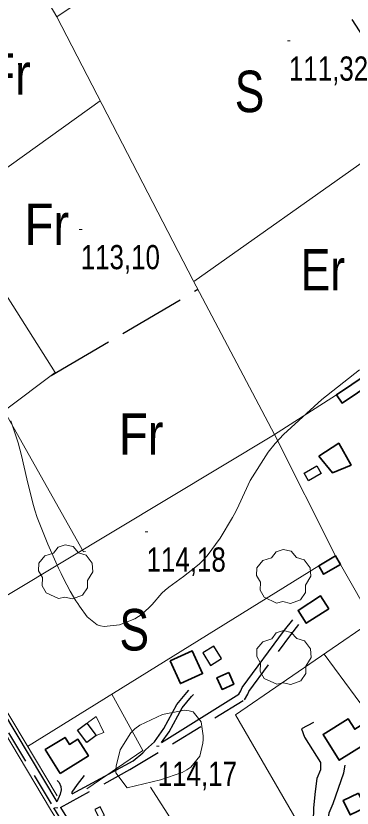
# Model space of a CAD drawing. Extents: x 487425 to 492029, y 4383576 to 4386788.
# Drawn here: x 490540.5 to 490662, y 4386018.5 to 4386304.9 of the extents above; entities that cross this region are included whole.
import ezdxf
from ezdxf.enums import TextEntityAlignment as Align

# ---------------------------------------------------------------- set-up
doc = ezdxf.new("R2010")
doc.units = 0
doc.header["$LTSCALE"] = 4
doc.linetypes.add('LONG_DASHED', pattern=[7.5, 6, -1.5])
doc.linetypes.add('MEDIUM_DASHED', pattern=[4.5, 3, -1.5])
for name, color, linetype, lineweight in [('21', 7, 'Continuous', 25), ('25', 7, 'LONG_DASHED', 25), ('29', 7, 'Continuous', 13), ('38', 7, 'Continuous', 25), ('47', 7, 'Continuous', 35), ('51', 7, 'Continuous', 13), ('7', 7, 'Continuous', 13), ('9', 7, 'Continuous', 13)]:
    doc.layers.add(name, color=color, linetype=linetype, lineweight=lineweight)
doc.layers.add('31', color=7, linetype='Continuous')

msp = doc.modelspace()

# ---------------------------------------------------------------- linework, layer by layer
at = {"layer": '21'}
for points in [[(490650.89, 4386139.47), (490646.27, 4386136.8), (490644.67, 4386139.56), (490649.29, 4386142.23)], [(490608.04, 4386074.58), (490610.86, 4386070.09), (490614.86, 4386072.61), (490612.04, 4386077.1)], [(490566.16, 4386049.22), (490569.52, 4386044.78), (490566.16, 4386042.23), (490562.79, 4386046.66)], [(490569.04, 4386018.01), (490570.63, 4386014.86), (490572.55, 4386015.83), (490570.96, 4386018.98)]]:
    msp.add_lwpolyline(points, close=True, dxfattribs=at)
at = {"layer": '25'}
for p, q in [((490629.52, 4386354.13), (490676.75, 4386280.46)), ((490553.28, 4386174.9), (490606.28, 4386206.06))]:
    msp.add_line(p, q, dxfattribs=at)
at = {"layer": '29'}
for points in [[(490555.93, 4386094.25), (490551.39, 4386096.37), (490549.98, 4386098.91), (490550.08, 4386101.89), (490548.71, 4386104.3), (490548.75, 4386107.05), (490550.91, 4386109.65), (490554.1, 4386110.65), (490555.75, 4386112.84), (490558.32, 4386113.67), (490561.18, 4386113.02), (490563.13, 4386110.75), (490565.94, 4386109.93), (490568.07, 4386107.08), (490568.31, 4386103.95), (490566.43, 4386100.8), (490566.43, 4386098.12), (490564.61, 4386095.51), (490560.99, 4386094.17), (490558.22, 4386094.8)], [(490634.73, 4386092.59), (490630.19, 4386094.71), (490628.78, 4386097.25), (490628.88, 4386100.23), (490627.51, 4386102.64), (490627.55, 4386105.39), (490629.71, 4386107.99), (490632.9, 4386108.99), (490634.55, 4386111.18), (490637.12, 4386112.01), (490639.98, 4386111.36), (490641.93, 4386109.09), (490644.74, 4386108.27), (490646.87, 4386105.42), (490647.11, 4386102.29), (490645.23, 4386099.14), (490645.23, 4386096.46), (490643.41, 4386093.85), (490639.79, 4386092.51), (490637.02, 4386093.14)], [(490634.79, 4386063.27), (490630.25, 4386065.39), (490628.84, 4386067.93), (490628.94, 4386070.91), (490627.57, 4386073.32), (490627.61, 4386076.07), (490629.77, 4386078.67), (490632.96, 4386079.67), (490634.61, 4386081.86), (490637.18, 4386082.69), (490640.04, 4386082.04), (490641.99, 4386079.77), (490644.8, 4386078.95), (490646.93, 4386076.1), (490647.17, 4386072.97), (490645.29, 4386069.82), (490645.29, 4386067.14), (490643.47, 4386064.53), (490639.85, 4386063.19), (490637.08, 4386063.82)]]:
    msp.add_lwpolyline(points, close=True, dxfattribs=at)
at = {"layer": '38', "linetype": 'MEDIUM_DASHED'}
msp.add_line((490556.58, 4386018.73), (490581.74, 4386032.41), dxfattribs=at)
at = {"layer": '38'}
for points in [[(490458.1, 4386192.65), (490473.89, 4386164.44), (490477.06, 4386159.29), (490478.72, 4386157.31), (490478.82, 4386156.45), (490478.96, 4386154.34), (490479.1, 4386151.81), (490479.32, 4386150.49), (490479.53, 4386149.03), (490479.9, 4386147.85), (490480.34, 4386145.7), (490481.44, 4386143.24), (490481.88, 4386141.61), (490483.93, 4386138.01), (490497.43, 4386116.24), (490530.41, 4386062.29), (490555.36, 4386020.73)], [(490593.1, 4386042.18), (490621.05, 4386059.68), (490621.76, 4386060.91), (490622.24, 4386062.11), (490637.63, 4386082.82), (490640.57, 4386086.57)], [(490560.87, 4386023.62), (490582.89, 4386035.6), (490586.38, 4386038.49), (490587.4, 4386039.58), (490590.55, 4386042.5), (490594.02, 4386047.29), (490598.71, 4386056.02), (490602.23, 4386060.29), (490603.01, 4386061.14)], [(490648.12, 4386049.49), (490643.76, 4386047.18), (490644.8, 4386044.18), (490650.62, 4386035.01), (490650.54, 4386032.31), (490649.33, 4386029.24), (490648.72, 4386024.52), (490648.1, 4386018.6), (490647.93, 4386013.65), (490647.3, 4386009.54)], [(490652.95, 4386010.31), (490653.79, 4386016.78), (490655.15, 4386020.23), (490659.08, 4386031.31), (490659.54, 4386034.08)], [(490560.87, 4386023.62), (490560.84, 4386024.33), (490562.72, 4386027.1), (490565.36, 4386030.24)], [(490555.45, 4386028.55), (490556.13, 4386027.8), (490556.72, 4386026.3), (490556.87, 4386025.1), (490556.49, 4386023.6), (490555.36, 4386020.73)], [(490556.58, 4386018.73), (490583.48, 4385975.5), (490583.94, 4385974.43), (490584.01, 4385974.39), (490585.05, 4385974.45), (490585.95, 4385974.66), (490586.6, 4385974.87), (490587.45, 4385975.16), (490590.25, 4385976.62)]]:
    msp.add_lwpolyline(points, dxfattribs=at)
at = {"layer": '38', "linetype": 'MEDIUM_DASHED'}
for points in [[(490505.07, 4386099.62), (490528.57, 4386061.18), (490554.09, 4386018.66), (490581.57, 4385974.5), (490582.24, 4385972.95), (490583.46, 4385972.21), (490583.77, 4385972.22)], [(490581.74, 4386032.41), (490623.13, 4386057.68), (490624.28, 4386059.68), (490624.7, 4386060.72), (490639.85, 4386081.12), (490642.77, 4386084.84)], [(490593.1, 4386042.18), (490595.93, 4386046.09), (490600.59, 4386054.76), (490603.93, 4386058.81), (490604.67, 4386059.62)]]:
    msp.add_lwpolyline(points, dxfattribs=at)
at = {"layer": '47'}
for points in [[(490656.35, 4386167.93), (490667.52, 4386175.42), (490669.56, 4386172.39), (490658.39, 4386164.9)], [(490649.98, 4386145.76), (490654.99, 4386139.67), (490661.67, 4386142.5), (490657.19, 4386150.38)], [(490649.94, 4386106.09), (490656.04, 4386109.64), (490657.81, 4386106.59), (490651.71, 4386103.04)], [(490653.56, 4386090.56), (490645.43, 4386085.36), (490642.47, 4386089.99), (490650.6, 4386095.19)], [(490596.22, 4386071.69), (490604.25, 4386075.35), (490607.98, 4386067.16), (490599.95, 4386063.5)], [(490617.43, 4386067.5), (490619.27, 4386063.31), (490615.01, 4386061.44), (490613.17, 4386065.63)], [(490670.74, 4386044.17), (490657.37, 4386035.81), (490651.52, 4386045.14), (490660.56, 4386050.81), (490662.95, 4386046.99), (490667.88, 4386050.08)], [(490556.51, 4386031.02), (490551.14, 4386039.66), (490558.27, 4386044.09), (490559.86, 4386041.52), (490562.95, 4386043.43), (490566.69, 4386037.35)], [(490664.31, 4386023.95), (490666.85, 4386018.77), (490661.36, 4386016.08), (490658.82, 4386021.27)]]:
    msp.add_lwpolyline(points, close=True, dxfattribs=at)
at = {"layer": '51'}
for p, q in [((490519.49, 4386237.33), (490571.01, 4386274.2)), ((490604.78, 4386208.89), (490688.52, 4386268.08)), ((490544.75, 4386040.79), (490649.94, 4386106.09)), ((490589.19, 4386026.05), (490611.98, 4385990.64))]:
    msp.add_line(p, q, dxfattribs=at)
for points in [[(490669.62, 4386380.93), (490555.31, 4386304.55), (490539.11, 4386332.14)], [(490555.31, 4386304.55), (490604.59, 4386209.25), (490633.96, 4386153.53), (490656.04, 4386109.64)], [(490532.71, 4386210.72), (490554.7, 4386175.96), (490536.29, 4386162.15), (490564.93, 4386111.15), (490565.63, 4386111.22)], [(490656.35, 4386167.93), (490633.58, 4386153.3), (490519.26, 4386084.59)], [(490651.97, 4386074.2), (490666.88, 4386053.86), (490684.52, 4386062.35), (490797.24, 4386132.97)], [(490493.84, 4386124.35), (490498.46, 4386116.88), (490531.45, 4386062.92), (490555.45, 4386022.97)], [(490657.81, 4386106.59), (490669.97, 4386085.19), (490684.07, 4386061.98), (490704.83, 4386033.05), (490729.32, 4385999.16), (490798.94, 4386038.24)], [(490505.35, 4386096.84), (490527.53, 4386060.55), (490553.06, 4386018.03), (490580.49, 4385973.94), (490581.08, 4385972.58)], [(490669.43, 4386086.15), (490619.93, 4386052.27), (490645.29, 4386008.41)], [(490566.09, 4386025.52), (490586.38, 4386039.33), (490575.18, 4386059.68)], [(490566.35, 4386049.36), (490569.47, 4386051.6), (490572.3, 4386045.89), (490569.52, 4386044.78)]]:
    msp.add_lwpolyline(points, dxfattribs=at)
at = {"layer": '7'}
for p, q in [((490638.69, 4386295.82), (490639.69, 4386295.82)), ((490563.43, 4386227.67), (490564.43, 4386227.67)), ((490587.24, 4386118.35), (490588.24, 4386118.35)), ((490591.28, 4386040.89), (490592.28, 4386040.89)), ((490554.62, 4386018.65), (490555.62, 4386018.65))]:
    msp.add_line(p, q, dxfattribs=at)
at = {"layer": '9'}
for points in [[(490563.55, 4386091.45), (490566.29, 4386087.61), (490569.87, 4386084.75), (490571.09, 4386084.36), (490572.4, 4386084.14), (490577.96, 4386084.76), (490583.54, 4386086.96), (490584.86, 4386087.72), (490586.09, 4386088.56), (490589.72, 4386092.15), (490593.29, 4386096.15), (490594.48, 4386097.25), (490595.76, 4386098.34), (490601.11, 4386102.23), (490606.74, 4386106.7), (490608.21, 4386108.15), (490609.62, 4386109.7), (490614.38, 4386116.06), (490618.77, 4386123.51), (490619.96, 4386125.73), (490621.13, 4386128.04), (490625.23, 4386136.96), (490631.64, 4386147.17), (490634.26, 4386150.28), (490637.24, 4386153.51), (490651.07, 4386166.21), (490664.64, 4386176.89)], [(490538.64, 4386158.52), (490541.31, 4386150.53), (490541.95, 4386148.27), (490542.56, 4386145.99), (490544.42, 4386137.57), (490546.57, 4386128.72), (490547.35, 4386126.18), (490548.21, 4386123.59), (490552.03, 4386113.88), (490555.91, 4386105.2), (490556.81, 4386103.26), (490557.65, 4386101.52), (490560.06, 4386096.91), (490562.2, 4386093.47), (490562.86, 4386092.47), (490563.55, 4386091.45)]]:
    msp.add_lwpolyline(points, dxfattribs=at)
msp.add_lwpolyline([(490580.67, 4386025.85), (490592.72, 4386028.71), (490600.65, 4386031.39), (490602.31, 4386032.29), (490603.74, 4386033.26), (490606.97, 4386037.32), (490608.1, 4386041.95), (490608.2, 4386043.29), (490608.21, 4386044.64), (490607.47, 4386049.71), (490604.52, 4386053.28), (490603.13, 4386053.69), (490601.5, 4386053.86), (490593.51, 4386052.38), (490585.32, 4386048.52), (490583.55, 4386047.2), (490582, 4386045.75), (490578.2, 4386039.6), (490576.7, 4386033.68), (490576.6, 4386032.38), (490576.64, 4386031.23)], close=True, dxfattribs=at)

# ---------------------------------------------------------------- texts
at = {"layer": '31'}
for s, width, p in [('Fr', 0.85, (490537.8, 4386276.38)), ('S', 0.8, (490624.95, 4386270.07)), ('Fr', 0.85, (490551.69, 4386222.05)), ('Er', 0.8, (490651.47, 4386205.63)), ('Fr', 0.85, (490585.79, 4386146.24)), ('S', 0.8, (490583.28, 4386075.49))]:
    msp.add_text(s, height=15, dxfattribs=dict(at, width=width)).set_placement(p, align=Align.CENTER)
at = {"layer": '7', "width": 0.8}
for s, p in [('111,32', (490639.19, 4386281.45)), ('113,10', (490563.93, 4386213.3)), ('114,18', (490587.74, 4386103.98)), ('114,17', (490591.78, 4386026.52))]:
    msp.add_text(s, height=8.75, dxfattribs=at).set_placement(p)

doc.saveas('drawing.dxf')
